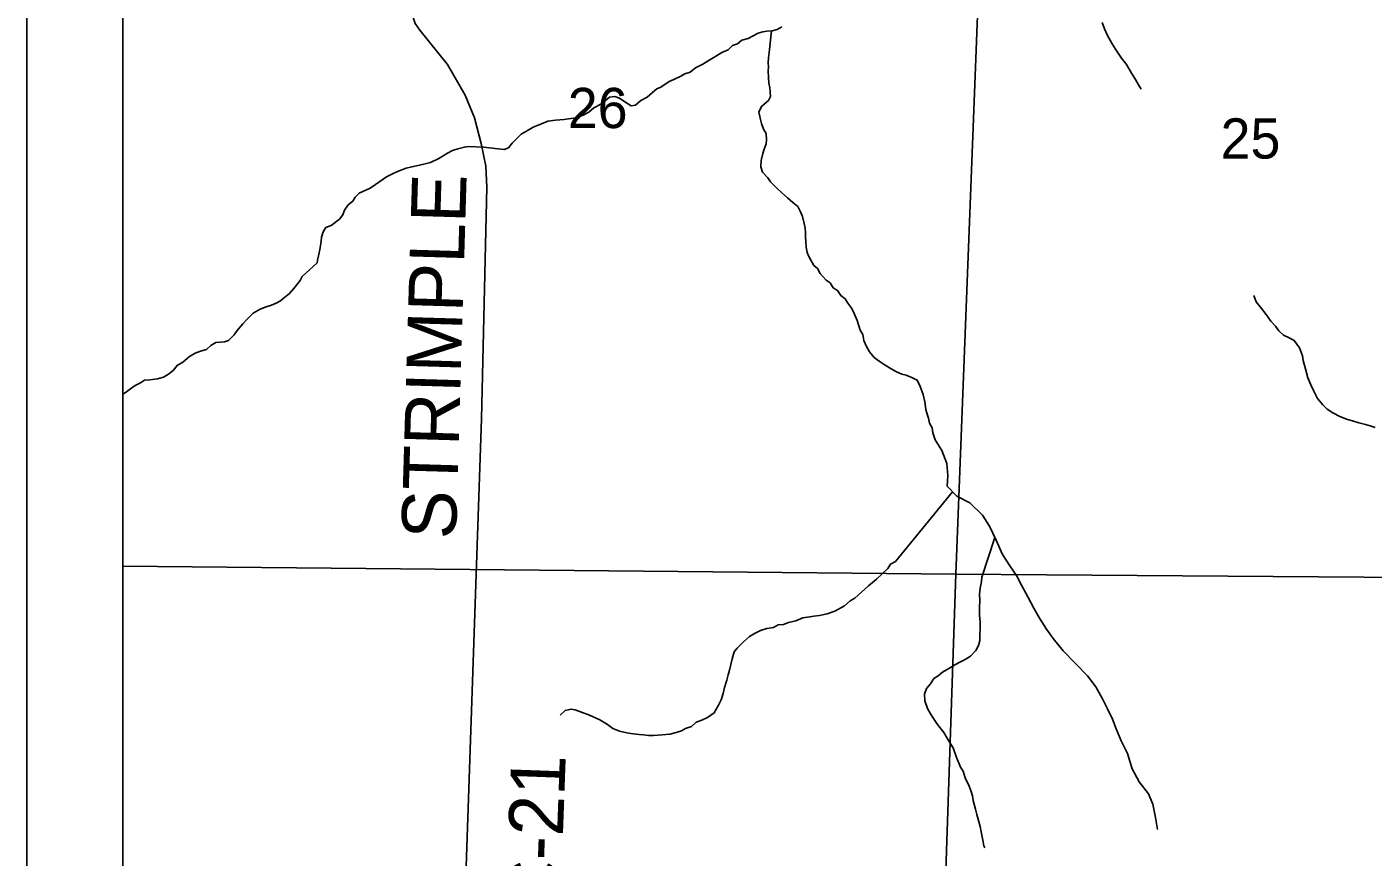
# Model space of a CAD drawing. Extents: x 0 to 34, y 0 to 22.
# Drawn here: x 2 to 3.401, y 18.515 to 19.379 of the extents above; entities that cross this region are included whole.
import ezdxf

# ---------------------------------------------------------------- set-up
doc = ezdxf.new("R2010")
doc.units = 0
for name, color, linetype in [('Default', 7, 'Continuous'), ('GM_X_County_Road', 7, 'Continuous'), ('GM_X_County_Road_Text', 7, 'Continuous'), ('GM_X_Minor_River', 7, 'Continuous'), ('GM_X_Section', 7, 'Continuous'), ('GM_X_Section_Text', 7, 'Continuous'), ('GM_X_State_Route', 7, 'Continuous'), ('SH_Data', 7, 'Continuous')]:
    doc.layers.add(name, color=color, linetype=linetype)

msp = doc.modelspace()

# ---------------------------------------------------------------- linework, layer by layer
at = {"layer": 'Default'}
for points in [[(2.1, 19.8111), (2.1, 18.8179), (2.9671, 18.8096), (3.0048, 19.785), (2.2447, 19.8069)], [(2.1, 18.8179), (2.1, 17.8244), (2.9334, 17.8114), (2.9671, 18.8096)]]:
    msp.add_lwpolyline(points, close=True, dxfattribs=at)
at = {"layer": 'GM_X_County_Road'}
msp.add_lwpolyline([(2.4536, 18.3939), (2.4734, 18.9711), (2.4789, 19.2126), (2.4779, 19.2343), (2.4729, 19.258), (2.466, 19.2847), (2.4564, 19.3082), (2.4379, 19.3402), (2.4089, 19.3759), (2.4042, 19.3829), (2.4024, 19.3879), (2.4033, 19.3939), (2.5108, 19.6061), (2.522, 19.6255), (2.5381, 19.646), (2.5504, 19.6643), (2.5583, 19.6763), (2.5688, 19.6992), (2.5863, 19.7508)], dxfattribs=at)
at = {"layer": 'GM_X_Minor_River'}
for points in [[(3.1194, 19.3838), (3.1218, 19.3773), (3.125, 19.3704), (3.13, 19.3618), (3.1332, 19.356), (3.1397, 19.3467), (3.1448, 19.34), (3.1498, 19.3311), (3.1542, 19.3245), (3.1574, 19.3191), (3.1601, 19.3143)], [(2.7859, 19.3794), (2.7809, 19.3766), (2.7759, 19.3752), (2.7702, 19.3747), (2.766, 19.374), (2.7614, 19.3727), (2.7509, 19.3673), (2.7444, 19.3653), (2.7397, 19.3617), (2.7347, 19.3599), (2.73, 19.3555), (2.7235, 19.3527), (2.718, 19.3491), (2.7091, 19.3441), (2.7037, 19.3405), (2.696, 19.3366), (2.6905, 19.3322), (2.6851, 19.3305), (2.6808, 19.328), (2.6735, 19.3244), (2.6685, 19.3223), (2.6599, 19.3165), (2.6557, 19.3148), (2.6514, 19.3111), (2.6459, 19.306), (2.639, 19.3028), (2.6335, 19.2977), (2.6289, 19.2971), (2.6215, 19.3019), (2.617, 19.3051), (2.6122, 19.3068), (2.6064, 19.3062), (2.5982, 19.2993), (2.5901, 19.295), (2.585, 19.2906), (2.5792, 19.2874), (2.5719, 19.2846), (2.5639, 19.2834), (2.5593, 19.2828), (2.5502, 19.282), (2.5422, 19.2811), (2.5356, 19.2783), (2.5271, 19.2748), (2.5217, 19.2719), (2.5147, 19.2676), (2.5096, 19.2628), (2.5053, 19.2584), (2.5013, 19.2532), (2.4967, 19.2515), (2.4907, 19.2525), (2.4816, 19.2532), (2.4752, 19.2541), (2.4596, 19.2547), (2.4554, 19.2541), (2.4485, 19.2524), (2.4432, 19.2507), (2.4378, 19.2478), (2.4288, 19.2424), (2.4203, 19.2382), (2.4161, 19.2372), (2.4088, 19.2352), (2.4008, 19.2335), (2.3947, 19.2322), (2.3874, 19.2294), (2.3812, 19.2266), (2.3743, 19.2231), (2.3673, 19.2184), (2.363, 19.2151), (2.3575, 19.2115), (2.346, 19.2062)], [(2.775, 19.3751), (2.7728, 19.3525), (2.7719, 19.3472), (2.7717, 19.3419), (2.7719, 19.3377), (2.7718, 19.3336), (2.7719, 19.3267), (2.7725, 19.3206), (2.7735, 19.316), (2.7737, 19.3118), (2.7743, 19.3069), (2.7719, 19.3028), (2.7652, 19.2969), (2.762, 19.291), (2.7632, 19.2841), (2.7646, 19.2787), (2.767, 19.2729), (2.7695, 19.2683), (2.7701, 19.2618), (2.7695, 19.2576), (2.7674, 19.252), (2.7661, 19.2475), (2.7644, 19.2403), (2.7641, 19.2335), (2.7659, 19.2281), (2.7713, 19.2222), (2.7742, 19.2179), (2.7805, 19.2116), (2.786, 19.2065), (2.7919, 19.2014), (2.7974, 19.1966), (2.8026, 19.1923), (2.8054, 19.1868), (2.8075, 19.1818), (2.8092, 19.1745), (2.8102, 19.1696), (2.8104, 19.165), (2.8106, 19.1608), (2.8108, 19.1555), (2.8114, 19.1501), (2.8123, 19.1444), (2.8141, 19.1402), (2.8191, 19.1309), (2.8231, 19.1277), (2.826, 19.1227), (2.8322, 19.1156), (2.8363, 19.1128), (2.8395, 19.1077), (2.844, 19.1049), (2.8472, 19.0995), (2.8517, 19.0963), (2.8545, 19.0916), (2.8589, 19.0862), (2.8614, 19.0808), (2.8642, 19.0738), (2.8676, 19.0634), (2.8701, 19.0592), (2.8714, 19.0527), (2.8739, 19.0473), (2.8771, 19.0411), (2.8822, 19.0352), (2.8874, 19.0312), (2.8926, 19.028), (2.8981, 19.0244), (2.9045, 19.0207), (2.9108, 19.0179), (2.9153, 19.0166), (2.9221, 19.0141), (2.9269, 19.0116), (2.9301, 19.005), (2.9329, 18.9966), (2.9349, 18.9889), (2.9357, 18.9809), (2.9371, 18.9763), (2.9385, 18.9721), (2.9398, 18.9667), (2.9423, 18.962), (2.9433, 18.9567), (2.9457, 18.9494)], [(2.346, 19.2062), (2.3416, 19.2021), (2.3392, 19.1977), (2.3345, 19.194), (2.3305, 19.1885), (2.3288, 19.1836), (2.3253, 19.1792), (2.3167, 19.1726), (2.3113, 19.1705), (2.3085, 19.166), (2.3068, 19.1604), (2.3063, 19.1562), (2.3053, 19.1494), (2.3035, 19.1411), (2.3025, 19.1366), (2.302, 19.1338)], [(2.302, 19.1338), (2.2864, 19.1193), (2.2843, 19.1152), (2.278, 19.1071), (2.2729, 19.1015), (2.2686, 19.0979), (2.2639, 19.0942), (2.2596, 19.0917), (2.2546, 19.0896), (2.2492, 19.0879), (2.2427, 19.0855), (2.2357, 19.0812), (2.2294, 19.0749), (2.2247, 19.0701), (2.2188, 19.0631), (2.2156, 19.0587), (2.21, 19.0528), (2.2058, 19.0514), (2.2013, 19.0512), (2.1967, 19.0506), (2.1916, 19.0477), (2.1869, 19.0433), (2.1808, 19.0416), (2.175, 19.0396), (2.1692, 19.0363), (2.1622, 19.0301), (2.1564, 19.0269), (2.1524, 19.0217), (2.1473, 19.0177), (2.1423, 19.0145), (2.1358, 19.0128), (2.1281, 19.0119), (2.1224, 19.0114), (2.1182, 19.0088), (2.1128, 19.006), (2.1077, 19.0024), (2.1022, 18.9984), (2.1, 18.9971)], [(3.2774, 19.0998), (3.2798, 19.0929), (3.2853, 19.0862), (3.29, 19.08), (3.2951, 19.073), (3.2998, 19.0679), (3.3034, 19.0628), (3.3082, 19.0584), (3.3134, 19.056), (3.3194, 19.0527), (3.3248, 19.0453), (3.328, 19.0369), (3.3286, 19.0319), (3.3313, 19.0219), (3.3336, 19.0139), (3.3368, 19.0065), (3.3396, 19.0007), (3.3435, 18.9926), (3.349, 18.986), (3.3538, 18.9812), (3.3597, 18.9776), (3.3668, 18.9736), (3.3747, 18.9706), (3.3799, 18.9693), (3.3867, 18.9672), (3.3935, 18.9654), (3.3984, 18.9641), (3.4036, 18.9624)], [(2.9457, 18.9494), (2.9524, 18.9382), (2.9577, 18.9248), (2.9589, 18.9122), (2.9582, 18.9012), (2.9681, 18.8907), (2.9816, 18.8838), (2.9949, 18.8709), (3.0022, 18.8597), (3.009, 18.845), (3.0158, 18.83), (3.0234, 18.8184), (3.0303, 18.8083), (3.0353, 18.7983), (3.0422, 18.7859), (3.0483, 18.7743), (3.0541, 18.7639), (3.0614, 18.7523), (3.0683, 18.7426), (3.0789, 18.7297), (3.104, 18.7039), (3.1128, 18.6923), (3.1197, 18.6799), (3.125, 18.6695), (3.1301, 18.6587), (3.1339, 18.6487), (3.1393, 18.636), (3.1457, 18.6229), (3.1506, 18.6068), (3.1578, 18.5933), (3.1677, 18.5808), (3.1723, 18.5701), (3.1749, 18.5563), (3.1769, 18.5437)], [(2.9637, 18.8954), (2.9041, 18.8228), (2.899, 18.8199)], [(3.0077, 18.8478), (2.9943, 18.8063), (2.9937, 18.8018), (2.9923, 18.795), (2.9918, 18.7889), (2.9919, 18.7821), (2.9916, 18.7749), (2.9917, 18.7665), (2.9923, 18.76), (2.9924, 18.7539), (2.9922, 18.7456), (2.992, 18.7407), (2.9907, 18.7354), (2.9878, 18.7302), (2.9823, 18.7243), (2.9769, 18.7207), (2.9718, 18.7182), (2.966, 18.7153), (2.9598, 18.7114), (2.9532, 18.7074), (2.9486, 18.7038), (2.9443, 18.7009), (2.9407, 18.6953), (2.9367, 18.6905), (2.9346, 18.6845), (2.9348, 18.6777), (2.9375, 18.6696), (2.9407, 18.6641), (2.944, 18.6595), (2.948, 18.6532), (2.9545, 18.6447), (2.9595, 18.6365), (2.9642, 18.6287), (2.9673, 18.6199), (2.9719, 18.6087), (2.9747, 18.6044), (2.9768, 18.5975), (2.981, 18.589), (2.9831, 18.5832), (2.9845, 18.579), (2.9851, 18.5741), (2.9874, 18.5649), (2.9888, 18.5595), (2.9908, 18.5533), (2.9925, 18.5468), (2.9934, 18.5415), (2.9954, 18.5311), (2.9964, 18.5269), (2.9971, 18.5247)], [(2.899, 18.8199), (2.8962, 18.8154), (2.8845, 18.8044), (2.8763, 18.7975), (2.8692, 18.7913), (2.8618, 18.7847), (2.8571, 18.7818), (2.8512, 18.7767), (2.8412, 18.771), (2.8331, 18.7682), (2.8251, 18.7666), (2.8194, 18.766), (2.8151, 18.765), (2.8079, 18.7641), (2.8006, 18.761), (2.7929, 18.7593), (2.7875, 18.7572), (2.7822, 18.7567), (2.7772, 18.7542), (2.7703, 18.7529), (2.7638, 18.7508), (2.758, 18.748), (2.7522, 18.7448), (2.7459, 18.7393), (2.7396, 18.7327), (2.7364, 18.7286), (2.7343, 18.7215), (2.7316, 18.7098), (2.7299, 18.7049), (2.7286, 18.6992), (2.7264, 18.6917), (2.7247, 18.6853), (2.7226, 18.6789), (2.7201, 18.6733), (2.7177, 18.6692), (2.7156, 18.6651), (2.7086, 18.6604), (2.7028, 18.6576), (2.6967, 18.6555), (2.692, 18.6511), (2.6858, 18.649), (2.6816, 18.6465), (2.6758, 18.6448), (2.6693, 18.6431), (2.6613, 18.6423), (2.6522, 18.6415), (2.6472, 18.6416), (2.6419, 18.6422), (2.6374, 18.6427), (2.6287, 18.6438), (2.6246, 18.6443), (2.617, 18.6461), (2.6099, 18.649), (2.6044, 18.653), (2.5965, 18.6578), (2.5857, 18.6628), (2.5763, 18.6661), (2.5707, 18.6682), (2.5666, 18.6691), (2.5604, 18.6678), (2.555, 18.6628)]]:
    msp.add_lwpolyline(points, dxfattribs=at)
at = {"layer": 'GM_X_Section'}
msp.add_lwpolyline([(3.9584, 18.8022), (2.9671, 18.8096), (3.0048, 19.785), (4.1378, 19.745)], dxfattribs=at)
msp.add_lwpolyline([(2.9671, 18.8096), (3.9584, 18.8022), (3.923, 17.7965), (2.9334, 17.8114)], close=True, dxfattribs=at)
at = {"layer": 'GM_X_State_Route'}
msp.add_lwpolyline([(3.4964, 19.7659), (3.3482, 19.7707), (3.2315, 19.7745), (3.1896, 19.7761), (3.0947, 19.7799), (3.0889, 19.7803), (3.0835, 19.7803), (3.0002, 19.7836), (2.608, 19.7955), (2.1, 19.8108), (2.1, 16.7408)], dxfattribs=at)
at = {"layer": 'SH_Data'}
for p, q in [((2, 21), (2, 14)), ((2.1, 20.9), (2.1, 14.1))]:
    msp.add_line(p, q, dxfattribs=at)

# ---------------------------------------------------------------- texts
at = {"layer": 'GM_X_County_Road_Text'}
for s, rotation, p in [('STRIMPLE', 88.3029, (2.4466, 18.8455)), ('C-21', 87.9423, (2.5551, 18.4561))]:
    msp.add_text(s, height=0.05682, rotation=rotation, dxfattribs=at).set_placement(p)
at = {"layer": 'GM_X_Section_Text'}
for s, p in [('26', (2.5631, 19.2739)), ('25', (3.2427, 19.2422))]:
    msp.add_text(s, height=0.04186, rotation=0, dxfattribs=at).set_placement(p)

doc.saveas('drawing.dxf')
